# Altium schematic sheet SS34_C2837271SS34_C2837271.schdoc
size 127 x 101 mm
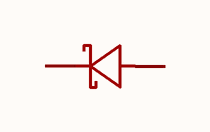
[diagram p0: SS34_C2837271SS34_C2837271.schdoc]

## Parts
D?  ss34_c2837271  [SMA_L4.2-W2.7-LS5.0-RD]  (value not drawn)

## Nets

Not connected (* = marked no-connect by the designer): D? 1(K) 2(A)

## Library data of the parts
D? = ss34_c2837271: 二极管配置:1个独立式;正向压降(Vf):550mV@3A;直流反向耐压(Vr):40V;整流电流:3A;; Manufacturer: JSMSEMI(杰盛微); ManufacturerPart: SS34; AddInBom: yes; ModelId: 65cb4bac5fcf4f9e9bc57087be833eeb; ModelTransform: 196.85,104.3305,0,0,0,0,0,0,0; Diode Configuration: 1个独立式; Voltage - DC Reverse(Vr): 40V; Current - Rectified: 3A; Operating Junction Temperature Range: -50℃~+125℃; Non-Repetitive Peak Forward Surge Current: 100A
